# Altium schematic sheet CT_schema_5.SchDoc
size 356 x 192 mm
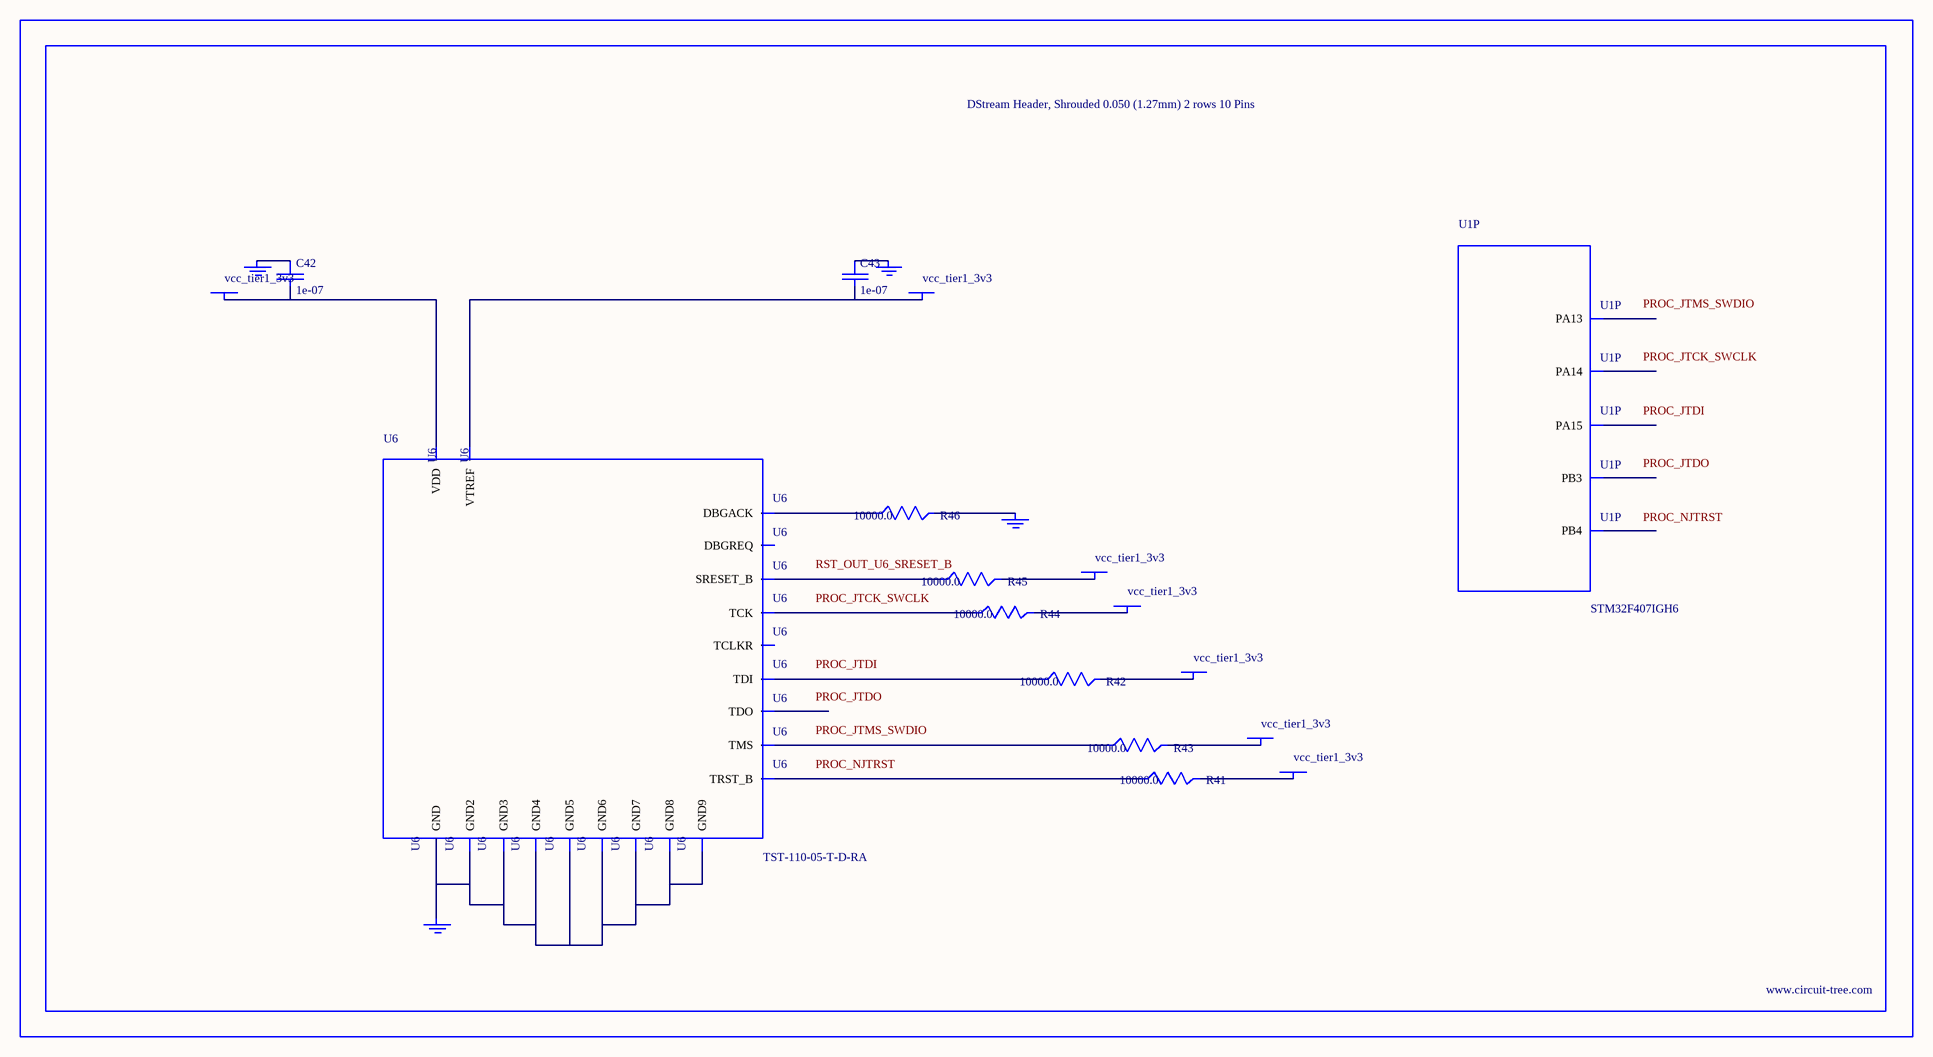
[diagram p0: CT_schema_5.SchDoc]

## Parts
BORDER4  (no value)
C42  1e-07  [C0402]
C43  1e-07  [C0402]
GND_INSTANCE_4_0  (no value)
GND_INSTANCE_4_1  (no value)
GND_INSTANCE_4_2  (no value)
GND_INSTANCE_4_3  (no value)
POWER_INSTANCE_4_0  vcc_tier1_3v3
POWER_INSTANCE_4_1  vcc_tier1_3v3
POWER_INSTANCE_4_2  vcc_tier1_3v3
POWER_INSTANCE_4_3  vcc_tier1_3v3
POWER_INSTANCE_4_4  vcc_tier1_3v3
POWER_INSTANCE_4_5  vcc_tier1_3v3
POWER_INSTANCE_4_6  vcc_tier1_3v3
R41  10000.0  [R0603]
R42  10000.0  [R0603]
R43  10000.0  [R0603]
R44  10000.0  [R0603]
R45  10000.0  [R0603]
R46  10000.0  [R0603]
U1  STM32F407IGH6  [UFBGA176]  (part P of 18)
U6  TST-110-05-T-D-RA  [TST-110-05-T-D-RA]

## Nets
NetC42_1: C42.1 GND_INSTANCE_4_1.0(GND)
NetC42_2: C42.2 POWER_INSTANCE_4_1.0(PWR) U6.2(VDD)
NetC43_1: C43.1 GND_INSTANCE_4_0.0(GND)
NetC43_2: C43.2 POWER_INSTANCE_4_0.0(PWR) U6.1(VTREF)
NetGND_INSTANCE_4_2_0: GND_INSTANCE_4_2.0(GND) R46.2
NetGND_INSTANCE_4_3_0: GND_INSTANCE_4_3.0(GND) U6.4(GND) U6.6(GND2) U6.8(GND3) U6.10(GND4) U6.12(GND5) U6.14(GND6) U6.16(GND7) U6.18(GND8) U6.20(GND9)
NetPOWER_INSTANCE_4_2_0: POWER_INSTANCE_4_2.0(PWR) R41.2
NetPOWER_INSTANCE_4_3_0: POWER_INSTANCE_4_3.0(PWR) R42.2
NetPOWER_INSTANCE_4_4_0: POWER_INSTANCE_4_4.0(PWR) R43.2
NetPOWER_INSTANCE_4_5_0: POWER_INSTANCE_4_5.0(PWR) R44.2
NetPOWER_INSTANCE_4_6_0: POWER_INSTANCE_4_6.0(PWR) R45.2
NetR41_1: R41.1 U6.3(TRST_B)
NetR42_1: R42.1 U6.5(TDI)
NetR43_1: R43.1 U6.7(TMS)
NetR44_1: R44.1 U6.9(TCK)
NetR45_1: R45.1 U6.15(SRESET_B)
NetR46_1: R46.1 U6.19(DBGACK)

Not connected (* = marked no-connect by the designer): U1 A9(PB4) A10(PB3) A13(PA15) A14(PA14) A15(PA13); U6 11(TCLKR) 13(TDO) 17(DBGREQ)

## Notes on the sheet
- Labels drawn without touching a wire or pin: PROC_JTCK_SWCLK, PROC_JTDI, PROC_JTDO, PROC_JTMS_SWDIO, PROC_NJTRST, RST_OUT_U6_SRESET_B

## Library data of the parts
BORDER4 = BORDER_PAGE4
C42 C43 = C0402C104K3RACTU
GND_INSTANCE_4_0-GND_INSTANCE_4_3 = GND
POWER_INSTANCE_4_0-POWER_INSTANCE_4_6 = PWR
R41-R46 = RC0603JR-0710KL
